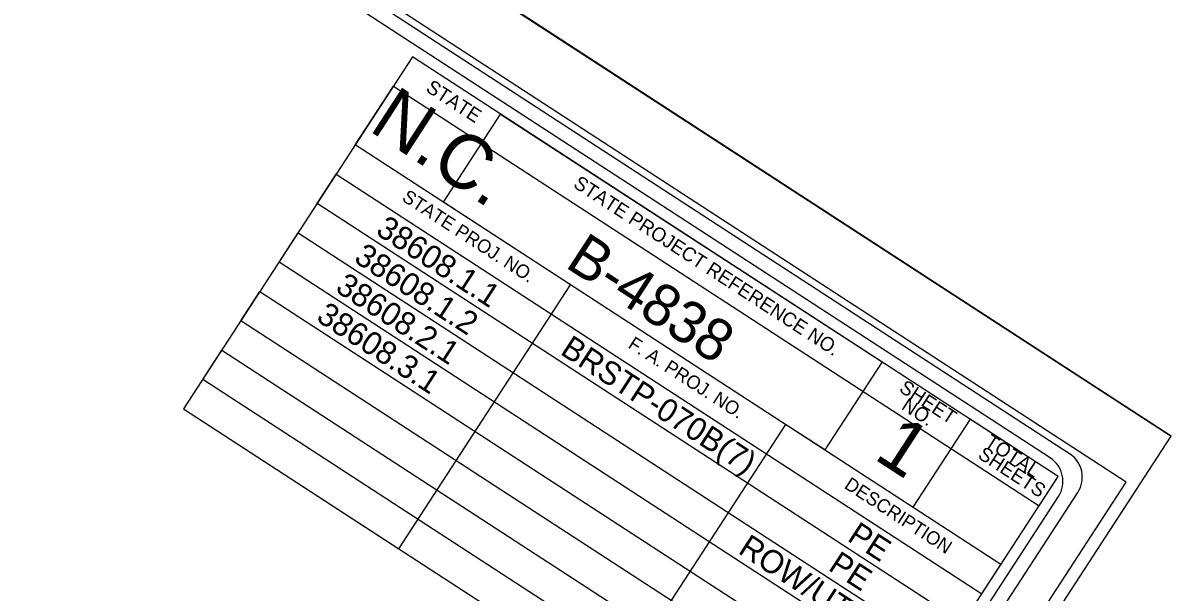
# Model space of a CAD drawing. Extents: x 2291197 to 2302790, y 592892 to 604246.
# Drawn here: x 2300199 to 2301839, y 600352 to 601165 of the extents above; entities that cross this region are included whole.
import ezdxf

# ---------------------------------------------------------------- set-up
doc = ezdxf.new("R2010")
doc.units = 0
for name, color, linetype in [('Sheet Cutting Line CELL', 7, 'Continuous'), ('Sheet Data Field CELL', 7, 'Continuous'), ('Sheet Plot Border Inside CELL', 7, 'Continuous'), ('Sheet Plot Border Outside CELL', 7, 'Continuous'), ('Sheet Title CELL', 7, 'Continuous')]:
    doc.layers.add(name, color=color, linetype=linetype)

msp = doc.modelspace()

# ---------------------------------------------------------------- linework, layer by layer
at = {"layer": 'Sheet Cutting Line CELL'}
msp.add_line((2296191.6, 604246.1), (2301839.2, 600574.8), dxfattribs=at)
at = {"layer": 'Sheet Plot Border Inside CELL'}
msp.add_lwpolyline([(2293886.1, 600604), (2299475, 596970.9), (2301775.2, 600509.4), (2296186.3, 604142.5)], close=True, dxfattribs=at)
at = {"layer": 'Sheet Plot Border Outside CELL'}
msp.add_lwpolyline([(2301839.2, 600574.8), (2296191.6, 604246.1), (2293793.6, 600557.1), (2299441.2, 596885.8)], close=True, dxfattribs=at)
at = {"layer": 'Sheet Title CELL'}
for points in [[(2301694.2, 600549.8), (2296730.7, 603776.5)], [(2301666.5, 600544), (2296904.3, 603639.7)], [(2301541.7, 600307.9), (2300619.4, 600907.4), (2300646.6, 600949.3), (2301568.9, 600349.8), (2301596.2, 600391.8), (2300673.9, 600991.3), (2300728.4, 601075.2), (2301650.7, 600475.6), (2301677.9, 600517.5), (2300755.7, 601117), (2300428.7, 600614), (2300736, 600414.2), (2300981.3, 600791.5), (2300799.7, 600909.5), (2300881.4, 601035.3), (2301426.4, 600681), (2301344.7, 600555.3), (2301288.7, 600591.7), (2301043.4, 600214.4)], [(2301487.2, 600224.1), (2300564.9, 600823.6), (2300592.1, 600865.5), (2301514.4, 600266)], [(2301432.7, 600140.2), (2300510.4, 600739.7), (2300537.7, 600781.7), (2301459.9, 600182.2)], [(2301378.2, 600056.4), (2300455.9, 600655.9), (2300483.1, 600697.8), (2301405.4, 600098.3)], [(2300428.7, 600614), (2301350.9, 600014.5)], [(2301350.9, 600014.5), (2301677.9, 600517.5), (2301552.2, 600599.3), (2301470.5, 600473.5)], [(2299460.6, 597040.5), (2301706.1, 600494.7)], [(2299858, 597688.5), (2301678.4, 600488.9)]]:
    msp.add_lwpolyline(points, dxfattribs=at)
for centre in [(2301644.8, 600510.6), (2301672.5, 600516.5)]:
    msp.add_arc(centre, 40, 326.9737, 56.9737, dxfattribs=at)

# ---------------------------------------------------------------- texts
at = {"layer": 'Sheet Data Field CELL'}
msp.add_text('B-4838', height=60, rotation=326.9737, dxfattribs=at).set_placement((2300971.9, 600817.6))
at = {"layer": 'Sheet Title CELL'}
for s, height, p in [('STATE', 20, (2300773.2, 601068.7)), ('N.C.', 77.4, (2300691.4, 601012.6)), ('STATE PROJECT REFERENCE NO.', 19.999, (2300983.9, 600931.7)), ('STATE PROJ. NO.', 19.2, (2300739.2, 600912.4)), ('38608.1.1', 33.02, (2300701.5, 600864.5)), ('38608.1.2', 33.02, (2300670.3, 600825.1)), ('38608.2.1', 33.02, (2300643.7, 600782.8)), ('38608.3.1', 33.02, (2300616.5, 600740.9)), ('BRSTP-070B(7)', 33.02, (2300965.1, 600693.1)), ('F. A. PROJ. NO.', 19.2, (2301062.2, 600702.4)), ('SHEET', 20, (2301449.4, 600639.8)), ('NO.', 20, (2301452.6, 600614.2)), ('1', 77.4, (2301412.8, 600543.7)), ('TOTAL', 20, (2301571.6, 600562.1)), ('SHEETS', 20, (2301561.9, 600544.6)), ('DESCRIPTION', 19.2, (2301371.1, 600501.6)), ('PE', 33.02, (2301375.2, 600426.5)), ('ROW/UTILITIES', 33.02, (2301219.2, 600408.7)), ('PE', 33.02, (2301348, 600384.6))]:
    msp.add_text(s, height=height, rotation=326.9737, dxfattribs=at).set_placement(p)

doc.saveas('drawing.dxf')
